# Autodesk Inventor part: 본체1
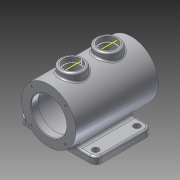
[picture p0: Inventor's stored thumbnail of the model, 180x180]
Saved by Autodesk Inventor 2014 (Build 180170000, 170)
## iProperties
Created: 2014-12
Part Number: 본체1
Material: 알루미늄 6061
Document SubType Name: Modeling
Designer: Owner
Density: 2.71 g/cm^3
Appearance: 알루미늄 - 평지
Mass: 1298.61 g
Surface Area: 1038.07 cm^2
Volume: 479.191 cm^3
Author: Owner
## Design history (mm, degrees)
sketch "스케치1"
  geometry: L1 (-70, 0)-(70, 0); L2 (-70, 30)-(-70, 46); L3 (-70, 46)-(70, 46); L4 (70, 46)-(70, 30); L5 (-58, 30)-(-58, 37.5); L6 (-58, 37.5)-(58, 37.5); L7 (58, 37.5)-(58, 30); L8 (-70, 30)-(-58, 30); L9 (58, 30)-(70, 30); 3 further points
  constraints: 18 end point, 9 perpendicular, 3 equal length, 2 midpoint, 1 coincident, 1 horizontal, 1 parallel, 1 vertical alignment
  dimensions: "d0" = 140 distance of L1.end L1.start; "d2" = 92 diameter of L3 L1; "d3" = 75 diameter of L6 L1; "d4" = 60 diameter of L8 L1; "d5" = 12 distance of L2.start L5.start
revolve "회전1" sketch "스케치1" stored, may be unused: angle "d6" = 90 deg
node "작업 평면1"
sketch "스케치3"
  geometry: L1 (0, 0)-(0, -50); L2 (-65, -50)-(65, -50); L3 (-65, -50)-(-65, -38); L4 (-65, -38)-(65, -38); L5 (65, -38)-(65, -50); C1 r 46 at (0, 0) reference; 2 further points
  constraints: 10 end point, 4 perpendicular, 3 coincident, 1 midpoint, 1 vertical
  dimensions: "d8" = 50 distance of L1.start L1.end; "d9" = 130 distance of L2.start L2.end; "d10" = 12 distance of L2.start L3.end
extrude "돌출1" join sketch "스케치3" distance "d11" = 95; taper "d12" = 0 deg
node "작업 평면2"
sketch "스케치5"
  geometry: L1 (46, -70)-(-46, -70) reference; L2 (46, 70)-(-46, 70) reference; C1 r 20 at (0, -30); C2 r 20 at (0, 30); 1 further point
  constraints: 2 centre point, 2 vertical alignment
  dimensions: "d14" = 40 diameter of C1; "d15" = 40 diameter of C2; "d16" = 40 distance from line of L1 C1.centre; "d17" = 40 distance from line of L2 C2.centre
extrude "돌출2" join sketch "스케치5" stored distance "d18" = 95; taper "d19" = 0 deg
sketch "스케치6"
  geometry: C1 r 20 at (0, 0) reference; C2 r 15 at (0, 0); 1 further point
  constraints: 1 centre point, 1 coincident
  dimensions: "d20" = 30 diameter of C2
extrude "돌출3" cut sketch "스케치6" distance "d21" = 8; taper "d22" = 0 deg
sketch "스케치7"
  geometry: C1 r 20 at (0, 0) reference; C2 r 15 at (0, 0); 1 further point
  constraints: 1 centre point, 1 coincident
  dimensions: "d23" = 30 diameter of C2
extrude "돌출4" cut sketch "스케치7" distance "d24" = 8; taper "d25" = 0 deg
sketch "스케치8"
  geometry: C1 r 15 at (0, 0) reference; C2 r 12.5 at (0, 0); 1 further point
  constraints: 1 centre point, 1 coincident
  dimensions: "d26" = 25 diameter of C2
extrude "돌출5" cut sketch "스케치8" stored distance "d27" = 5; taper "d28" = 0 deg
sketch "스케치9"
  geometry: C1 r 15 at (0, 0) reference; C2 r 12.5 at (0, 0); 1 further point
  constraints: 1 centre point, 1 coincident
  dimensions: "d29" = 25 diameter of C2
extrude "돌출6" cut sketch "스케치9" stored distance "d30" = 5; taper "d31" = 0 deg
fillet "모깎기1" dims "d32" = 10
sketch "스케치13"
  geometry: L1 (110, 0)-(0, 0) reference; L2 (120, 10)-(120, 85) reference; L3 (-10, 10)-(-10, 85) reference; L4 (101, -15)-(9, -15) reference; L5 (101, 125)-(9, 125) reference; L6 (29.077, 95)-(80.923, 95) reference; L7 (80.923, 95)-(80.923, 0) reference; L8 (80.923, 0)-(29.077, 0) reference; L9 (29.077, 0)-(29.077, 95) reference; L10 (55, 125)-(55, -15); C1 r 5.5 at (107, 12.5); C2 r 5.5 at (3, 12.5); 3 further points
  constraints: 2 centre point, 2 end point, 2 midpoint, 2 other
  dimensions: "d53" = 12.5 distance from line of L1 C1.centre; "d54" = 11 diameter of C1; "d59" = 13 distance from line of L2 C1.centre; "d60" = 11 diameter of C2; "d61" = 12.5 distance from line of L1 C2.centre; "d62" = 13 distance from line of L3 C2.centre
extrude "돌출8" cut sketch "스케치13" stored distance "d63" = 5; taper "d64" = 0 deg
sketch "스케치14"
  geometry: L1 (120, 10)-(120, 85) reference; L2 (0, 95)-(110, 95) reference; L3 (-10, 10)-(-10, 85) reference; C1 r 5.5 at (107, 82.5); C2 r 5.5 at (3, 82.5); 1 further point
  constraints: 2 centre point
  dimensions: "d74" = 13 distance from line of L1 C1.centre; "d75" = 12.5 distance from line of L2 C1.centre; "d76" = 13 distance from line of L3 C2.centre; "d77" = 12.5 distance from line of L2 C2.centre; "d78" = 11 diameter of C2; "d79" = 11 diameter of C1
extrude "돌출9" cut sketch "스케치14" stored distance "d80" = 5; taper "d81" = 0 deg
sketch "스케치15" dims "d111" = 3.242, "d113" = 4, "d114" = 2, "d116" = 10
  geometry: L1 (-39.077, 10)-(-39.077, 85) reference; C1 r 5.5 at (-26.077, 82.5) reference; 2 further points
  constraints: 1 other
  dimensions: "d82" = 35 vertical distance of C1.centre point (-31.077, 47.5); "d83" = 8 distance from line of L1 point (-31.077, 47.5)
feature "엠보싱1" sketch "스케치15" dims "d0" = 140, "d2" = 92, "d3" = 75, "d4" = 60, "d5" = 12, "d8" = 50, "d9" = 130, "d10" = 12, "d84" = 1, "d85" = 0
fillet "모깎기2" dims "d86" = 3
fillet "모깎기3" dims "d87" = 5
chamfer "모따기1" distance "d88" = 1; stored, may be unused: second distance "d89" = 2, angle "d90" = 45 deg
chamfer "모따기2" distance "d91" = 1; stored, may be unused: second distance "d92" = 2, angle "d93" = 45 deg
fillet "모깎기4" dims "d94" = 3
fillet "모깎기5" dims "d95" = 3
fillet "모깎기6" dims "d96" = 3
sketch "스케치16"
  geometry: L1 (0, 0)-(-60.354, 0); L2 (0, 0)-(-28.284, 28.284); C1 r 31 at (0, 0) reference; 1 further point
  constraints: 4 end point, 1 coincident, 1 horizontal
  dimensions: "d97" = 40 distance of L1.start L2.end; "d98" = 45 deg angle of L1 L2
hole "구멍1" sketch "스케치16" at (-28.284, 28.284) diameter "d99" = 3.242; stored, may be unused: countersink angle "d103" = 90 deg, drill point angle "d105" = 118 deg; dims "d100" = 8, "d101" = 4, "d102" = 2, "d104" = 10
sketch "스케치17"
  geometry: L1 (0, 0)-(-28.284, 28.284); L2 (0, 0)-(-40.31, 0); C1 r 31 at (0, 0) reference; 1 further point
  constraints: 4 end point, 1 coincident, 1 horizontal
  dimensions: "d109" = 45 deg angle of L2 L1; "d110" = 40 distance of L1.start L1.end
hole "구멍2" sketch "스케치17" at (-28.284, 28.284) diameter "d111" = 3.242; stored, may be unused: countersink angle "d115" = 90 deg, drill point angle "d117" = 118 deg; dims "d112" = 8, "d113" = 4, "d114" = 2, "d116" = 10
sketch "스케치18"
  geometry: L1 (-10, 53)-(-50, 53) reference; L2 (-45, 56)-(-45, 48) reference; L3 (-15, 56)-(-15, 48) reference; L4 (15, 56)-(15, 48) reference; L5 (50, 53)-(10, 53) reference; L6 (-70, -46)-(70, -46) reference; L7 (-55, -41)-(-55, -50) reference; A1 r 5 centre (-60, -51) between (-55.101, -50) and (-60, -46) reference; A2 r 5 centre (45, -51) between (45, -46) and (40.101, -50) reference; 1 further point
node "솔리드1"
pattern_circular "원형 패턴1" dims angle "d107" = 360 deg
pattern_circular "원형 패턴2" dims angle "d119" = 360 deg
node "투영된 루프1"
other parameters: "d7" = -15, "d13" = 56
